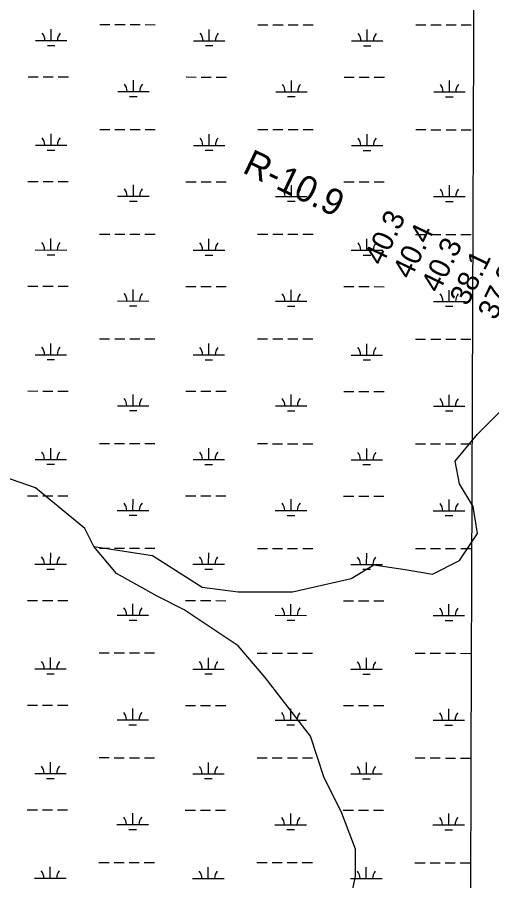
# Model space of a CAD drawing. Extents: x 3148686 to 3186545, y 916144 to 941516.
# Drawn here: x 3154122 to 3155629, y 930245 to 932988 of the extents above; entities that cross this region are included whole.
import ezdxf

# ---------------------------------------------------------------- set-up
doc = ezdxf.new("R2010")
doc.units = 0
for name, color, linetype in [('V-GRID-MAJR', 7, 'Continuous'), ('V-RIVR-RANG', 7, 'Continuous'), ('V-RIVR-RANG-IDEN', 7, 'Continuous'), ('V-TOPO-SHOR', 7, 'Continuous'), ('V-WETL-SWMP', 7, 'Continuous')]:
    doc.layers.add(name, color=color, linetype=linetype)

msp = doc.modelspace()

# ---------------------------------------------------------------- linework, layer by layer
at = {"layer": 'V-GRID-MAJR'}
msp.add_spline([(3155532.8, 921545.6), (3155553.9, 927607.5), (3155575.1, 933670.5), (3155596.3, 939733.5), (3155596.3, 939734.6)], degree=3, dxfattribs=at)
at = {"layer": 'V-TOPO-SHOR'}
for points in [[(3154365.2, 931306.4), (3154551.5, 931277.5), (3154709.1, 931177), (3154823.7, 931162.6), (3154995.7, 931162.4), (3155182.1, 931205.2), (3155253.8, 931248.1), (3155354.2, 931233.7), (3155440.2, 931219.2), (3155526.2, 931262.2), (3155583.6, 931348.1), (3155569.4, 931434.1), (3155526.5, 931505.8), (3155512.2, 931577.5), (3155584, 931663.4), (3155655.7, 931735)], [(3155181.1, 930187.5), (3155195.5, 930259.1), (3155195.6, 930345.1), (3155152.7, 930459.8), (3155095.5, 930574.6), (3155052.6, 930703.6), (3154909.5, 930890.1), (3154823.6, 930990.5), (3154651.7, 931105.4), (3154565.7, 931148.5), (3154436.8, 931220.3), (3154365.2, 931306.4), (3154336.6, 931363.7), (3154179, 931492.9), (3154053.1, 931536.9)]]:
    msp.add_lwpolyline(points, dxfattribs=at)
at = {"layer": 'V-WETL-SWMP'}
for p, q in [((3154384, 932964.5), (3154416, 932964.5)), ((3154432, 932964.5), (3154464, 932964.4)), ((3154480, 932964.4), (3154512, 932964.4)), ((3154528, 932964.4), (3154560, 932964.3)), ((3154885.9, 932964), (3154917.9, 932964)), ((3154933.9, 932963.9), (3154965.9, 932963.9)), ((3154981.9, 932963.9), (3155013.9, 932963.9)), ((3155029.9, 932963.8), (3155061.9, 932963.8)), ((3155387.8, 932963.5), (3155419.8, 932963.4)), ((3155435.8, 932963.4), (3155467.8, 932963.4)), ((3155483.8, 932963.4), (3155515.8, 932963.3)), ((3155531.8, 932963.3), (3155563.8, 932963.3)), ((3154229.4, 932913.9), (3154229.4, 932949.9)), ((3154731.3, 932913.4), (3154731.3, 932949.4)), ((3155233.2, 932912.9), (3155233.2, 932948.9)), ((3154179.4, 932914), (3154279.4, 932913.9)), ((3154681.3, 932913.5), (3154781.3, 932913.4)), ((3155183.2, 932912.9), (3155283.2, 932912.8)), ((3154217.4, 932898.5), (3154241.4, 932898.5)), ((3154719.3, 932898), (3154743.3, 932898)), ((3155221.2, 932897.5), (3155245.2, 932897.4)), ((3154155.9, 932798.6), (3154187.9, 932798.6)), ((3154203.9, 932798.5), (3154235.9, 932798.5)), ((3154251.9, 932798.5), (3154283.9, 932798.4)), ((3154490.7, 932751.8), (3154490.7, 932787.8)), ((3154657.8, 932798.1), (3154689.8, 932798)), ((3154705.8, 932798), (3154737.8, 932798)), ((3154753.8, 932798), (3154785.8, 932797.9)), ((3154992.6, 932751.3), (3154992.6, 932787.3)), ((3155159.7, 932797.5), (3155191.7, 932797.5)), ((3155207.7, 932797.5), (3155239.7, 932797.4)), ((3155255.7, 932797.4), (3155287.7, 932797.4)), ((3155494.5, 932750.7), (3155494.5, 932786.7)), ((3154440.7, 932751.9), (3154540.7, 932751.7)), ((3154942.6, 932751.3), (3155042.6, 932751.2)), ((3155444.5, 932750.8), (3155544.5, 932750.7)), ((3154478.6, 932736.4), (3154502.6, 932736.4)), ((3154980.5, 932735.9), (3155004.5, 932735.8)), ((3155482.4, 932735.3), (3155506.4, 932735.3)), ((3154229, 932581.3), (3154229.1, 932617.3)), ((3154383.7, 932631.8), (3154415.7, 932631.8)), ((3154431.7, 932631.8), (3154463.7, 932631.8)), ((3154479.7, 932631.7), (3154511.7, 932631.7)), ((3154527.7, 932631.7), (3154559.7, 932631.7)), ((3154730.9, 932580.7), (3154731, 932616.7)), ((3154885.6, 932631.3), (3154917.6, 932631.3)), ((3154933.6, 932631.3), (3154965.6, 932631.2)), ((3154981.6, 932631.2), (3155013.6, 932631.2)), ((3155029.6, 932631.2), (3155061.6, 932631.1)), ((3155232.8, 932580.2), (3155232.9, 932616.2)), ((3155387.5, 932630.8), (3155419.5, 932630.8)), ((3155435.5, 932630.7), (3155467.5, 932630.7)), ((3155483.5, 932630.7), (3155515.5, 932630.7)), ((3155531.5, 932630.6), (3155563.5, 932630.6)), ((3154179, 932581.3), (3154279, 932581.2)), ((3154680.9, 932580.8), (3154780.9, 932580.7)), ((3155182.8, 932580.3), (3155282.8, 932580.2)), ((3154217, 932565.8), (3154241, 932565.8)), ((3154718.9, 932565.3), (3154742.9, 932565.3)), ((3155220.8, 932564.8), (3155244.8, 932564.8)), ((3154155.5, 932465.9), (3154187.5, 932465.9)), ((3154203.5, 932465.9), (3154235.5, 932465.8)), ((3154251.5, 932465.8), (3154283.5, 932465.8)), ((3154490.3, 932419.1), (3154490.3, 932455.1)), ((3154657.4, 932465.4), (3154689.4, 932465.3)), ((3154705.4, 932465.3), (3154737.4, 932465.3)), ((3154753.4, 932465.3), (3154785.4, 932465.2)), ((3154992.2, 932418.6), (3154992.2, 932454.6)), ((3155159.3, 932464.9), (3155191.3, 932464.8)), ((3155207.3, 932464.8), (3155239.3, 932464.8)), ((3155255.3, 932464.8), (3155287.3, 932464.7)), ((3155494.1, 932418.1), (3155494.2, 932454.1)), ((3154440.3, 932419.2), (3154540.3, 932419.1)), ((3154942.2, 932418.7), (3155042.2, 932418.5)), ((3155444.1, 932418.1), (3155544.1, 932418)), ((3154478.3, 932403.7), (3154502.3, 932403.7)), ((3154980.2, 932403.2), (3155004.2, 932403.2)), ((3155482.1, 932402.7), (3155506.1, 932402.6)), ((3154228.7, 932248.6), (3154228.7, 932284.6)), ((3154383.3, 932299.2), (3154415.3, 932299.1)), ((3154431.3, 932299.1), (3154463.3, 932299.1)), ((3154479.3, 932299.1), (3154511.3, 932299)), ((3154527.3, 932299), (3154559.3, 932299)), ((3154730.6, 932248.1), (3154730.6, 932284.1)), ((3154885.2, 932298.6), (3154917.2, 932298.6)), ((3154933.2, 932298.6), (3154965.2, 932298.6)), ((3154981.2, 932298.5), (3155013.2, 932298.5)), ((3155029.2, 932298.5), (3155061.2, 932298.5)), ((3155232.5, 932247.5), (3155232.5, 932283.5)), ((3155387.1, 932298.1), (3155419.1, 932298.1)), ((3155435.1, 932298.1), (3155467.1, 932298)), ((3155483.1, 932298), (3155515.1, 932298)), ((3155531.1, 932298), (3155563.1, 932297.9)), ((3154178.7, 932248.6), (3154278.7, 932248.5)), ((3154216.7, 932233.2), (3154240.7, 932233.1)), ((3154680.6, 932248.1), (3154780.6, 932248)), ((3154718.6, 932232.6), (3154742.6, 932232.6)), ((3155182.5, 932247.6), (3155282.5, 932247.5)), ((3155220.5, 932232.1), (3155244.5, 932232.1)), ((3154155.2, 932133.2), (3154187.2, 932133.2)), ((3154203.2, 932133.2), (3154235.2, 932133.2)), ((3154251.2, 932133.1), (3154283.2, 932133.1)), ((3154489.9, 932086.5), (3154490, 932122.5)), ((3154657.1, 932132.7), (3154689.1, 932132.7)), ((3154705.1, 932132.7), (3154737.1, 932132.6)), ((3154753.1, 932132.6), (3154785.1, 932132.6)), ((3154991.9, 932085.9), (3154991.9, 932121.9)), ((3155159, 932132.2), (3155191, 932132.1)), ((3155207, 932132.1), (3155239, 932132.1)), ((3155255, 932132.1), (3155287, 932132)), ((3155493.8, 932085.4), (3155493.8, 932121.4)), ((3154439.9, 932086.5), (3154539.9, 932086.4)), ((3154941.9, 932086), (3155041.9, 932085.9)), ((3155443.8, 932085.4), (3155543.8, 932085.3)), ((3154477.9, 932071), (3154501.9, 932071)), ((3154979.8, 932070.5), (3155003.8, 932070.5)), ((3155481.7, 932070), (3155505.7, 932070)), ((3154228.3, 931915.9), (3154228.4, 931951.9)), ((3154383, 931966.5), (3154415, 931966.5)), ((3154431, 931966.4), (3154463, 931966.4)), ((3154479, 931966.4), (3154511, 931966.4)), ((3154527, 931966.3), (3154559, 931966.3)), ((3154730.2, 931915.4), (3154730.3, 931951.4)), ((3154884.9, 931966), (3154916.9, 931965.9)), ((3154932.9, 931965.9), (3154964.9, 931965.9)), ((3154980.9, 931965.9), (3155012.9, 931965.8)), ((3155028.9, 931965.8), (3155060.9, 931965.8)), ((3155232.1, 931914.9), (3155232.2, 931950.9)), ((3155386.8, 931965.4), (3155418.8, 931965.4)), ((3155434.8, 931965.4), (3155466.8, 931965.4)), ((3155482.8, 931965.3), (3155514.8, 931965.3)), ((3155530.8, 931965.3), (3155562.8, 931965.3)), ((3154178.3, 931916), (3154278.3, 931915.9)), ((3154216.3, 931900.5), (3154240.3, 931900.5)), ((3154680.2, 931915.4), (3154780.2, 931915.3)), ((3154718.2, 931900), (3154742.2, 931899.9)), ((3155182.1, 931914.9), (3155282.1, 931914.8)), ((3155220.1, 931899.4), (3155244.1, 931899.4)), ((3154154.8, 931800.6), (3154186.8, 931800.5)), ((3154202.8, 931800.5), (3154234.8, 931800.5)), ((3154250.8, 931800.5), (3154282.8, 931800.4)), ((3154489.6, 931753.8), (3154489.6, 931789.8)), ((3154656.7, 931800), (3154688.7, 931800)), ((3154704.7, 931800), (3154736.7, 931799.9)), ((3154752.7, 931799.9), (3154784.7, 931799.9)), ((3154991.5, 931753.2), (3154991.5, 931789.2)), ((3155158.6, 931799.5), (3155190.6, 931799.5)), ((3155206.6, 931799.5), (3155238.6, 931799.4)), ((3155254.6, 931799.4), (3155286.6, 931799.4)), ((3155493.4, 931752.7), (3155493.5, 931788.7)), ((3154439.6, 931753.8), (3154539.6, 931753.7)), ((3154477.6, 931738.4), (3154501.6, 931738.3)), ((3154941.5, 931753.3), (3155041.5, 931753.2)), ((3154979.5, 931737.8), (3155003.5, 931737.8)), ((3155443.4, 931752.8), (3155543.4, 931752.7)), ((3155481.4, 931737.3), (3155505.4, 931737.3)), ((3154228, 931583.2), (3154228, 931619.2)), ((3154382.6, 931633.8), (3154414.6, 931633.8)), ((3154430.6, 931633.8), (3154462.6, 931633.7)), ((3154478.6, 931633.7), (3154510.6, 931633.7)), ((3154526.6, 931633.7), (3154558.6, 931633.6)), ((3154729.9, 931582.7), (3154729.9, 931618.7)), ((3154884.5, 931633.3), (3154916.5, 931633.3)), ((3154932.5, 931633.2), (3154964.5, 931633.2)), ((3154980.5, 931633.2), (3155012.5, 931633.2)), ((3155028.5, 931633.1), (3155060.5, 931633.1)), ((3155386.4, 931632.8), (3155418.4, 931632.7)), ((3155434.4, 931632.7), (3155466.4, 931632.7)), ((3155482.4, 931632.7), (3155514.4, 931632.6)), ((3155530.4, 931632.6), (3155562.4, 931632.6)), ((3155231.8, 931582.2), (3155231.8, 931618.2)), ((3154178, 931583.3), (3154278, 931583.2)), ((3154216, 931567.8), (3154240, 931567.8)), ((3154679.9, 931582.8), (3154779.9, 931582.7)), ((3154717.9, 931567.3), (3154741.9, 931567.3)), ((3155181.8, 931582.2), (3155281.8, 931582.1)), ((3155219.8, 931566.8), (3155243.8, 931566.7)), ((3154154.5, 931467.9), (3154186.5, 931467.9)), ((3154202.5, 931467.8), (3154234.5, 931467.8)), ((3154250.5, 931467.8), (3154282.5, 931467.8)), ((3154489.2, 931421.1), (3154489.3, 931457.1)), ((3154656.4, 931467.4), (3154688.4, 931467.3)), ((3154704.4, 931467.3), (3154736.4, 931467.3)), ((3154752.4, 931467.3), (3154784.4, 931467.2)), ((3154991.2, 931420.6), (3154991.2, 931456.6)), ((3155158.3, 931466.8), (3155190.3, 931466.8)), ((3155206.3, 931466.8), (3155238.3, 931466.7)), ((3155254.3, 931466.7), (3155286.3, 931466.7)), ((3155493.1, 931420), (3155493.1, 931456)), ((3154439.2, 931421.2), (3154539.2, 931421)), ((3154477.2, 931405.7), (3154501.2, 931405.7)), ((3154941.2, 931420.6), (3155041.2, 931420.5)), ((3154979.1, 931405.2), (3155003.1, 931405.1)), ((3155443.1, 931420.1), (3155543.1, 931420)), ((3155481, 931404.6), (3155505, 931404.6)), ((3154382.3, 931301.1), (3154414.3, 931301.1)), ((3154430.3, 931301.1), (3154462.3, 931301.1)), ((3154478.3, 931301), (3154510.3, 931301)), ((3154526.3, 931301), (3154558.3, 931301)), ((3154884.2, 931300.6), (3154916.2, 931300.6)), ((3154932.2, 931300.6), (3154964.2, 931300.5)), ((3154980.2, 931300.5), (3155012.2, 931300.5)), ((3155028.2, 931300.5), (3155060.2, 931300.4)), ((3155386.1, 931300.1), (3155418.1, 931300.1)), ((3155434.1, 931300), (3155466.1, 931300)), ((3155482.1, 931300), (3155514.1, 931300)), ((3155530.1, 931299.9), (3155562.1, 931299.9)), ((3154227.6, 931250.6), (3154227.7, 931286.6)), ((3154729.5, 931250), (3154729.6, 931286)), ((3155231.4, 931249.5), (3155231.5, 931285.5)), ((3154177.6, 931250.6), (3154277.6, 931250.5)), ((3154215.6, 931235.1), (3154239.6, 931235.1)), ((3154679.5, 931250.1), (3154779.5, 931250)), ((3155181.4, 931249.6), (3155281.4, 931249.5)), ((3154717.5, 931234.6), (3154741.5, 931234.6)), ((3155219.4, 931234.1), (3155243.4, 931234.1)), ((3154154.1, 931135.2), (3154186.1, 931135.2)), ((3154202.1, 931135.2), (3154234.1, 931135.1)), ((3154250.1, 931135.1), (3154282.1, 931135.1)), ((3154656, 931134.7), (3154688, 931134.6)), ((3154704, 931134.6), (3154736, 931134.6)), ((3154752, 931134.6), (3154784, 931134.5)), ((3155157.9, 931134.2), (3155189.9, 931134.1)), ((3155205.9, 931134.1), (3155237.9, 931134.1)), ((3155253.9, 931134.1), (3155285.9, 931134)), ((3154488.9, 931088.4), (3154488.9, 931124.4)), ((3154990.8, 931087.9), (3154990.8, 931123.9)), ((3155492.7, 931087.4), (3155492.8, 931123.4)), ((3154438.9, 931088.5), (3154538.9, 931088.4)), ((3154476.9, 931073), (3154500.9, 931073)), ((3154940.8, 931088), (3155040.8, 931087.8)), ((3154978.8, 931072.5), (3155002.8, 931072.5)), ((3155442.7, 931087.4), (3155542.7, 931087.3)), ((3155480.7, 931072), (3155504.7, 931071.9)), ((3154381.9, 930968.5), (3154413.9, 930968.4)), ((3154429.9, 930968.4), (3154461.9, 930968.4)), ((3154477.9, 930968.4), (3154509.9, 930968.3)), ((3154525.9, 930968.3), (3154557.9, 930968.3)), ((3154883.8, 930967.9), (3154915.8, 930967.9)), ((3154931.8, 930967.9), (3154963.8, 930967.9)), ((3154979.8, 930967.8), (3155011.8, 930967.8)), ((3155027.8, 930967.8), (3155059.8, 930967.8)), ((3155385.7, 930967.4), (3155417.7, 930967.4)), ((3155433.7, 930967.4), (3155465.7, 930967.3)), ((3155481.7, 930967.3), (3155513.7, 930967.3)), ((3155529.7, 930967.3), (3155561.7, 930967.2)), ((3154227.3, 930917.9), (3154227.3, 930953.9)), ((3154729.2, 930917.4), (3154729.2, 930953.4)), ((3155231.1, 930916.8), (3155231.1, 930952.8)), ((3154177.3, 930917.9), (3154277.3, 930917.8)), ((3154679.2, 930917.4), (3154779.2, 930917.3)), ((3155181.1, 930916.9), (3155281.1, 930916.8)), ((3154215.3, 930902.5), (3154239.3, 930902.4)), ((3154717.2, 930901.9), (3154741.2, 930901.9)), ((3155219.1, 930901.4), (3155243.1, 930901.4)), ((3154153.8, 930802.5), (3154185.8, 930802.5)), ((3154201.8, 930802.5), (3154233.8, 930802.5)), ((3154249.8, 930802.4), (3154281.8, 930802.4)), ((3154655.7, 930802), (3154687.7, 930802)), ((3154703.7, 930802), (3154735.7, 930801.9)), ((3154751.7, 930801.9), (3154783.7, 930801.9)), ((3155157.6, 930801.5), (3155189.6, 930801.4)), ((3155205.6, 930801.4), (3155237.6, 930801.4)), ((3155253.6, 930801.4), (3155285.6, 930801.3)), ((3154488.5, 930755.8), (3154488.6, 930791.8)), ((3154990.5, 930755.2), (3154990.5, 930791.2)), ((3155492.4, 930754.7), (3155492.4, 930790.7)), ((3154438.5, 930755.8), (3154538.5, 930755.7)), ((3154940.5, 930755.3), (3155040.5, 930755.2)), ((3155442.4, 930754.7), (3155542.4, 930754.6)), ((3154476.5, 930740.3), (3154500.5, 930740.3)), ((3154978.4, 930739.8), (3155002.4, 930739.8)), ((3155480.3, 930739.3), (3155504.3, 930739.3)), ((3154381.6, 930635.8), (3154413.6, 930635.8)), ((3154429.6, 930635.7), (3154461.6, 930635.7)), ((3154477.6, 930635.7), (3154509.6, 930635.7)), ((3154525.6, 930635.6), (3154557.6, 930635.6)), ((3154883.5, 930635.3), (3154915.5, 930635.2)), ((3154931.5, 930635.2), (3154963.5, 930635.2)), ((3154979.5, 930635.2), (3155011.5, 930635.1)), ((3155027.5, 930635.1), (3155059.5, 930635.1)), ((3155385.4, 930634.7), (3155417.4, 930634.7)), ((3155433.4, 930634.7), (3155465.4, 930634.7)), ((3155481.4, 930634.6), (3155513.4, 930634.6)), ((3155529.4, 930634.6), (3155561.4, 930634.6)), ((3154226.9, 930585.2), (3154227, 930621.2)), ((3154728.8, 930584.7), (3154728.9, 930620.7)), ((3155230.7, 930584.2), (3155230.8, 930620.2)), ((3154176.9, 930585.3), (3154276.9, 930585.2)), ((3154678.8, 930584.7), (3154778.8, 930584.6)), ((3155180.7, 930584.2), (3155280.7, 930584.1)), ((3154214.9, 930569.8), (3154238.9, 930569.8)), ((3154716.8, 930569.3), (3154740.8, 930569.2)), ((3155218.7, 930568.7), (3155242.7, 930568.7)), ((3154153.4, 930469.9), (3154185.4, 930469.8)), ((3154201.4, 930469.8), (3154233.4, 930469.8)), ((3154249.4, 930469.8), (3154281.4, 930469.7)), ((3154655.3, 930469.3), (3154687.3, 930469.3)), ((3154703.3, 930469.3), (3154735.3, 930469.2)), ((3154751.3, 930469.2), (3154783.3, 930469.2)), ((3155157.2, 930468.8), (3155189.2, 930468.8)), ((3155205.2, 930468.8), (3155237.2, 930468.7)), ((3155253.2, 930468.7), (3155285.2, 930468.7)), ((3154488.2, 930423.1), (3154488.2, 930459.1)), ((3154990.1, 930422.5), (3154990.1, 930458.5)), ((3155492, 930422), (3155492, 930458)), ((3154438.2, 930423.1), (3154538.2, 930423)), ((3154940.1, 930422.6), (3155040.1, 930422.5)), ((3155442, 930422.1), (3155542, 930422)), ((3154476.2, 930407.7), (3154500.2, 930407.6)), ((3154978.1, 930407.1), (3155002.1, 930407.1)), ((3155480, 930406.6), (3155504, 930406.6)), ((3154381.2, 930303.1), (3154413.2, 930303.1)), ((3154429.2, 930303.1), (3154461.2, 930303)), ((3154477.2, 930303), (3154509.2, 930303)), ((3154525.2, 930303), (3154557.2, 930302.9)), ((3154883.1, 930302.6), (3154915.1, 930302.6)), ((3154931.1, 930302.5), (3154963.1, 930302.5)), ((3154979.1, 930302.5), (3155011.1, 930302.5)), ((3155027.1, 930302.4), (3155059.1, 930302.4)), ((3155385, 930302.1), (3155417, 930302)), ((3155433, 930302), (3155465, 930302)), ((3154226.6, 930252.5), (3154226.6, 930288.5)), ((3154728.5, 930252), (3154728.5, 930288)), ((3155230.4, 930251.5), (3155230.4, 930287.5)), ((3155481, 930302), (3155513, 930301.9)), ((3155529, 930301.9), (3155561, 930301.9)), ((3154176.6, 930252.6), (3154276.6, 930252.5)), ((3154678.5, 930252.1), (3154778.5, 930252)), ((3155180.4, 930251.5), (3155280.4, 930251.4))]:
    msp.add_line(p, q, dxfattribs=at)
for centre, start, end in [((3154174.1, 932914.5), 359.1678, 40.7115), ((3154284.6, 932914.4), 139.1678, 180.7115), ((3154676.1, 932913.9), 359.1678, 40.7115), ((3154786.5, 932913.8), 139.1678, 180.7115), ((3155178, 932913.4), 359.1678, 40.7115), ((3155288.4, 932913.3), 139.1678, 180.7115), ((3154435.4, 932752.3), 359.1678, 40.7115), ((3154545.9, 932752.2), 139.1678, 180.7115), ((3154937.3, 932751.8), 359.1678, 40.7115), ((3155047.8, 932751.7), 139.1678, 180.7115), ((3155439.2, 932751.3), 359.1678, 40.7115), ((3155549.7, 932751.2), 139.1678, 180.7115), ((3154173.8, 932581.8), 359.1678, 40.7115), ((3154284.3, 932581.7), 139.1678, 180.7115), ((3154675.7, 932581.3), 359.1678, 40.7115), ((3154786.2, 932581.2), 139.1678, 180.7115), ((3155177.6, 932580.7), 359.1678, 40.7115), ((3155288.1, 932580.6), 139.1678, 180.7115), ((3154435.1, 932419.7), 359.1678, 40.7115), ((3154545.5, 932419.5), 139.1678, 180.7115), ((3154937, 932419.1), 359.1678, 40.7115), ((3155047.5, 932419), 139.1678, 180.7115), ((3155438.9, 932418.6), 359.1678, 40.7115), ((3155549.4, 932418.5), 139.1678, 180.7115), ((3154173.4, 932249.1), 359.1678, 40.7115), ((3154283.9, 932249), 139.1678, 180.7115), ((3154675.3, 932248.6), 359.1678, 40.7115), ((3154785.8, 932248.5), 139.1678, 180.7115), ((3155177.3, 932248.1), 359.1678, 40.7115), ((3155287.7, 932247.9), 139.1678, 180.7115), ((3154434.7, 932087), 359.1678, 40.7115), ((3154545.2, 932086.9), 139.1678, 180.7115), ((3154936.6, 932086.5), 359.1678, 40.7115), ((3155047.1, 932086.3), 139.1678, 180.7115), ((3155438.5, 932085.9), 359.1678, 40.7115), ((3155549, 932085.8), 139.1678, 180.7115), ((3154173.1, 931916.4), 359.1678, 40.7115), ((3154283.6, 931916.3), 139.1678, 180.7115), ((3154675, 931915.9), 359.1678, 40.7115), ((3154785.5, 931915.8), 139.1678, 180.7115), ((3155176.9, 931915.4), 359.1678, 40.7115), ((3155287.4, 931915.3), 139.1678, 180.7115), ((3154434.4, 931754.3), 359.1678, 40.7115), ((3154544.8, 931754.2), 139.1678, 180.7115), ((3154936.3, 931753.8), 359.1678, 40.7115), ((3155046.7, 931753.7), 139.1678, 180.7115), ((3155438.2, 931753.3), 359.1678, 40.7115), ((3155548.7, 931753.1), 139.1678, 180.7115), ((3154172.7, 931583.8), 359.1678, 40.7115), ((3154283.2, 931583.7), 139.1678, 180.7115), ((3154674.6, 931583.2), 359.1678, 40.7115), ((3154785.1, 931583.1), 139.1678, 180.7115), ((3155176.6, 931582.7), 359.1678, 40.7115), ((3155287, 931582.6), 139.1678, 180.7115), ((3154434, 931421.6), 359.1678, 40.7115), ((3154544.5, 931421.5), 139.1678, 180.7115), ((3154935.9, 931421.1), 359.1678, 40.7115), ((3155046.4, 931421), 139.1678, 180.7115), ((3155437.8, 931420.6), 359.1678, 40.7115), ((3155548.3, 931420.5), 139.1678, 180.7115), ((3154172.4, 931251.1), 359.1678, 40.7115), ((3154282.9, 931251), 139.1678, 180.7115), ((3154674.3, 931250.6), 359.1678, 40.7115), ((3154784.8, 931250.5), 139.1678, 180.7115), ((3155176.2, 931250), 359.1678, 40.7115), ((3155286.7, 931249.9), 139.1678, 180.7115), ((3154433.7, 931089), 359.1678, 40.7115), ((3154544.1, 931088.8), 139.1678, 180.7115), ((3154935.6, 931088.4), 359.1678, 40.7115), ((3155046, 931088.3), 139.1678, 180.7115), ((3155437.5, 931087.9), 359.1678, 40.7115), ((3155548, 931087.8), 139.1678, 180.7115), ((3154172, 930918.4), 359.1678, 40.7115), ((3154282.5, 930918.3), 139.1678, 180.7115), ((3154673.9, 930917.9), 359.1678, 40.7115), ((3154784.4, 930917.8), 139.1678, 180.7115), ((3155175.9, 930917.4), 359.1678, 40.7115), ((3155286.3, 930917.2), 139.1678, 180.7115), ((3154433.3, 930756.3), 359.1678, 40.7115), ((3154543.8, 930756.2), 139.1678, 180.7115), ((3154935.2, 930755.8), 359.1678, 40.7115), ((3155045.7, 930755.6), 139.1678, 180.7115), ((3155437.1, 930755.2), 359.1678, 40.7115), ((3155547.6, 930755.1), 139.1678, 180.7115), ((3154171.7, 930585.7), 359.1678, 40.7115), ((3154282.2, 930585.6), 139.1678, 180.7115), ((3154673.6, 930585.2), 359.1678, 40.7115), ((3154784.1, 930585.1), 139.1678, 180.7115), ((3155175.5, 930584.7), 359.1678, 40.7115), ((3155286, 930584.6), 139.1678, 180.7115), ((3154433, 930423.6), 359.1678, 40.7115), ((3154543.4, 930423.5), 139.1678, 180.7115), ((3154934.9, 930423.1), 359.1678, 40.7115), ((3155045.3, 930423), 139.1678, 180.7115), ((3155436.8, 930422.6), 359.1678, 40.7115), ((3155547.3, 930422.4), 139.1678, 180.7115), ((3154171.3, 930253.1), 359.1678, 40.7115), ((3154281.8, 930253), 139.1678, 180.7115), ((3154673.2, 930252.5), 359.1678, 40.7115), ((3154783.7, 930252.4), 139.1678, 180.7115), ((3155175.2, 930252), 359.1678, 40.7115), ((3155285.6, 930251.9), 139.1678, 180.7115)]:
    msp.add_arc(centre, 35.2, start, end, dxfattribs=at)

# ---------------------------------------------------------------- texts
at = {"layer": 'V-RIVR-RANG'}
for s, p in [('40.3', (3155280.7, 932195.8)), ('40.4', (3155370.8, 932152.5)), ('40.3', (3155461, 932109.2)), ('38.1', (3155552.2, 932068.1)), ('37.2', (3155641.3, 932022.7))]:
    msp.add_text(s, height=67, rotation=64.2183, dxfattribs=at).set_placement(p)
at = {"layer": 'V-RIVR-RANG-IDEN'}
msp.add_text('R-10.9', height=83, rotation=334.3645, dxfattribs=at).set_placement((3154833.3, 932495.9))

doc.saveas('drawing.dxf')
